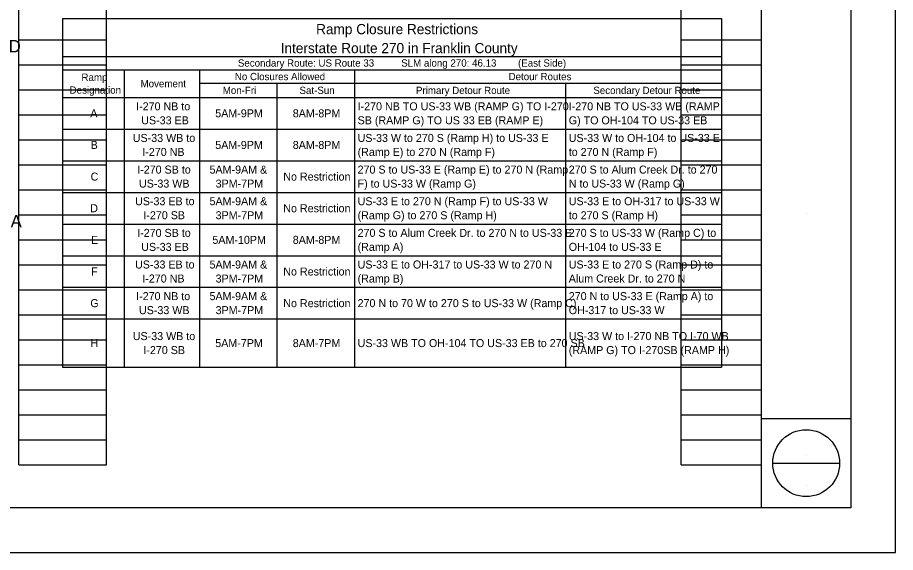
# Model space of a CAD drawing. Extents: x 0 to 34, y 0 to 22.
# Drawn here: x 24.17 to 34, y 0 to 5.99 of the extents above; entities that cross this region are included whole.
import ezdxf

# ---------------------------------------------------------------- set-up
doc = ezdxf.new("R2010")
doc.units = 0
for name, color, linetype in [('BD_P_Text', 7, 'Continuous'), ('Default', 7, 'Continuous'), ('SH_Border', 7, 'Continuous'), ('SH_Cut_Line', 7, 'Continuous'), ('SH_Data', 7, 'Continuous')]:
    doc.layers.add(name, color=color, linetype=linetype)

msp = doc.modelspace()

# ---------------------------------------------------------------- linework, layer by layer
at = {"layer": 'Default'}
for p, q in [((24.67, 5.9816), (32.05, 5.9816)), ((24.67, 5.9816), (24.67, 2.0745)), ((32.05, 5.9816), (32.05, 2.0745)), ((24.67, 5.5563), (32.05, 5.5563)), ((24.67, 5.4057), (32.05, 5.4057)), ((25.361, 5.4057), (25.361, 2.0745)), ((26.2027, 5.4057), (26.2027, 2.0745)), ((27.9392, 5.4057), (27.9392, 2.0745)), ((26.2027, 5.2551), (32.05, 5.2551)), ((27.0709, 5.2551), (27.0709, 2.0745)), ((30.3047, 5.2551), (30.3047, 2.0745)), ((24.67, 5.0956), (32.05, 5.0956)), ((24.67, 4.7412), (32.05, 4.7412)), ((24.67, 4.3868), (32.05, 4.3868)), ((24.67, 4.0325), (32.05, 4.0325)), ((24.67, 3.6781), (32.05, 3.6781)), ((24.67, 3.3237), (32.05, 3.3237)), ((24.67, 2.9693), (32.05, 2.9693)), ((24.67, 2.6149), (32.05, 2.6149)), ((24.67, 2.0745), (32.05, 2.0745))]:
    msp.add_line(p, q, dxfattribs=at)
at = {"layer": 'SH_Border'}
for p, q in [((32.5, 0.5), (32.5, 21.5)), ((32.5, 1.5), (33.5, 1.5))]:
    msp.add_line(p, q, dxfattribs=at)
msp.add_lwpolyline([(2, 21.5), (33.5, 21.5), (33.5, 0.5), (2, 0.5)], close=True, dxfattribs=at)
at = {"layer": 'SH_Cut_Line'}
msp.add_lwpolyline([(0, 0), (34, 0), (34, 22), (0, 22)], close=True, dxfattribs=at)
at = {"layer": 'SH_Data'}
for p, q in [((24.18, 0.98), (24.18, 21.14)), ((25.16, 0.98), (25.16, 21.14)), ((31.6, 0.98), (31.6, 21.14)), ((32.5, 0.98), (32.5, 21.14)), ((24.18, 5.74), (25.16, 5.74)), ((31.6, 5.74), (32.5, 5.74)), ((24.18, 5.46), (25.16, 5.46)), ((31.6, 5.46), (32.5, 5.46)), ((24.18, 5.18), (25.16, 5.18)), ((31.6, 5.18), (32.5, 5.18)), ((24.18, 4.9), (25.16, 4.9)), ((31.6, 4.9), (32.5, 4.9)), ((24.18, 4.62), (25.16, 4.62)), ((31.6, 4.62), (32.5, 4.62)), ((24.18, 4.34), (25.16, 4.34)), ((31.6, 4.34), (32.5, 4.34)), ((24.18, 4.06), (25.16, 4.06)), ((31.6, 4.06), (32.5, 4.06)), ((24.18, 3.78), (25.16, 3.78)), ((31.6, 3.78), (32.5, 3.78)), ((33, 3.7917), (33, 3.7917)), ((24.18, 3.5), (25.16, 3.5)), ((31.6, 3.5), (32.5, 3.5)), ((24.18, 3.22), (25.16, 3.22)), ((31.6, 3.22), (32.5, 3.22)), ((24.18, 2.94), (25.16, 2.94)), ((31.6, 2.94), (32.5, 2.94)), ((24.18, 2.66), (25.16, 2.66)), ((31.6, 2.66), (32.5, 2.66)), ((24.18, 2.38), (25.16, 2.38)), ((31.6, 2.38), (32.5, 2.38)), ((24.18, 2.1), (25.16, 2.1)), ((31.6, 2.1), (32.5, 2.1)), ((24.18, 1.82), (25.16, 1.82)), ((31.6, 1.82), (32.5, 1.82)), ((24.18, 1.54), (25.16, 1.54)), ((31.6, 1.54), (32.5, 1.54)), ((24.18, 1.26), (25.16, 1.26)), ((31.6, 1.26), (32.5, 1.26)), ((33, 1.085), (33, 1.085)), ((32.625, 1), (33.375, 1)), ((24.18, 0.98), (25.16, 0.98)), ((31.6, 0.98), (32.5, 0.98)), ((33, 0.745), (33, 0.745))]:
    msp.add_line(p, q, dxfattribs=at)
msp.add_circle((33, 1), 0.375, dxfattribs=at)

# ---------------------------------------------------------------- texts
at = {"layer": 'BD_P_Text'}
for s, p in [('DAMAGED ', (23.2546, 5.6)), ('A ', (24.0879, 3.64))]:
    msp.add_text(s, height=0.14, dxfattribs=at).set_placement(p)
at = {"layer": 'Default'}
for s, height, p in [('Ramp Closure Restrictions', 0.114111, (27.5097, 5.8044)), ('Interstate Route 270 in Franklin County', 0.114111, (27.1128, 5.5917)), ('Secondary Route: US Route 33          SLM along 270: 46.13        (East Side)', 0.081508, (26.6333, 5.4411)), ('Ramp', 0.08151, (24.8809, 5.2812)), ('No Closures Allowed', 0.081508, (26.5991, 5.2896)), ('Detour Routes', 0.081508, (29.6662, 5.2896)), ('Designation', 0.081508, (24.7485, 5.1386)), ('Movement', 0.08151, (25.5431, 5.2099)), ('Mon-Fri', 0.08151, (26.4638, 5.1346)), ('Sat-Sun', 0.08151, (27.3235, 5.1346)), ('Primary Detour Route', 0.081508, (28.6286, 5.1346)), ('Secondary Detour Route', 0.081508, (30.6156, 5.1346)), ('I-270 NB to', 0.089659, (25.4934, 4.952)), ('I-270 NB TO US-33 WB (RAMP G) TO I-270', 0.089659, (27.9746, 4.952)), ('I-270 NB TO US-33 WB (RAMP', 0.089659, (30.3401, 4.952)), ('A', 0.0897, (24.9798, 4.8736)), ('5AM-9PM', 0.08966, (26.3799, 4.8736)), ('8AM-8PM', 0.08966, (27.2482, 4.8736)), ('US-33 EB', 0.08966, (25.5508, 4.7951)), ('SB (RAMP G) TO US 33 EB (RAMP E)', 0.089659, (27.9746, 4.7951)), ('G) TO OH-104 TO US-33 EB', 0.089659, (30.3401, 4.7951)), ('US-33 WB to', 0.089659, (25.4561, 4.5977)), ('US-33 W to 270 S (Ramp H) to US-33 E', 0.089659, (27.9746, 4.5977)), ('US-33 W to OH-104 to US-33 E', 0.089659, (30.3401, 4.5977)), ('B', 0.0897, (24.9837, 4.5192)), ('I-270 NB', 0.08966, (25.5626, 4.4408)), ('5AM-9PM', 0.08966, (26.3799, 4.5192)), ('8AM-8PM', 0.08966, (27.2482, 4.5192)), ('(Ramp E) to 270 N (Ramp F)', 0.089659, (27.9746, 4.4408)), ('to 270 N (Ramp F)', 0.089659, (30.3401, 4.4408)), ('I-270 SB to', 0.089659, (25.5052, 4.2433)), ('5AM-9AM &', 0.08966, (26.3156, 4.2433)), ('270 S to US-33 E (Ramp E) to 270 N (Ramp', 0.089659, (27.9746, 4.2433)), ('270 S to Alum Creek Dr. to 270', 0.089659, (30.3401, 4.2433)), ('C', 0.0897, (24.9834, 4.1648)), ('No Restriction', 0.089659, (27.142, 4.1648)), ('US-33 WB', 0.08966, (25.5252, 4.0864)), ('3PM-7PM', 0.08966, (26.3839, 4.0864)), ('F) to US-33 W (Ramp G)', 0.089659, (27.9746, 4.0864)), ('N to US-33 W (Ramp G)', 0.089659, (30.3401, 4.0864)), ('US-33 EB to', 0.089659, (25.4816, 3.8889)), ('5AM-9AM &', 0.08966, (26.3156, 3.8889)), ('US-33 E to 270 N (Ramp F) to US-33 W', 0.089659, (27.9746, 3.8889)), ('US-33 E to OH-317 to US-33 W', 0.089659, (30.3401, 3.8889)), ('D', 0.0897, (24.9793, 3.8104)), ('No Restriction', 0.089659, (27.142, 3.8104)), ('I-270 SB', 0.08966, (25.5744, 3.732)), ('3PM-7PM', 0.08966, (26.3839, 3.732)), ('(Ramp G) to 270 S (Ramp H)', 0.089659, (27.9746, 3.732)), ('to 270 S (Ramp H)', 0.089659, (30.3401, 3.732)), ('E', 0.0897, (24.9878, 3.4561)), ('I-270 SB to', 0.089659, (25.5052, 3.5345)), ('5AM-10PM', 0.08966, (26.3477, 3.4561)), ('8AM-8PM', 0.08966, (27.2482, 3.4561)), ('270 S to Alum Creek Dr. to 270 N to US-33 E', 0.089659, (27.9746, 3.5345)), ('270 S to US-33 W (Ramp C) to', 0.089659, (30.3401, 3.5345)), ('US-33 EB', 0.08966, (25.5508, 3.3776)), ('(Ramp A)', 0.08966, (27.9746, 3.3776)), ('OH-104 to US-33 E', 0.089659, (30.3401, 3.3776)), ('US-33 EB to', 0.089659, (25.4816, 3.1801)), ('5AM-9AM &', 0.08966, (26.3156, 3.1801)), ('US-33 E to OH-317 to US-33 W to 270 N', 0.089659, (27.9746, 3.1801)), ('US-33 E to 270 S (Ramp D) to', 0.089659, (30.3401, 3.1801)), ('F', 0.0897, (24.9891, 3.1017)), ('No Restriction', 0.089659, (27.142, 3.1017)), ('I-270 NB', 0.08966, (25.5626, 3.0232)), ('3PM-7PM', 0.08966, (26.3839, 3.0232)), ('(Ramp B)', 0.08966, (27.9746, 3.0232)), ('Alum Creek Dr. to 270 N', 0.089659, (30.3401, 3.0232)), ('I-270 NB to', 0.089659, (25.4934, 2.8258)), ('5AM-9AM &', 0.08966, (26.3156, 2.8258)), ('270 N to US-33 E (Ramp A) to', 0.089659, (30.3401, 2.8258)), ('G', 0.0897, (24.98, 2.7473)), ('US-33 WB', 0.08966, (25.5252, 2.6688)), ('3PM-7PM', 0.08966, (26.3839, 2.6688)), ('No Restriction', 0.089659, (27.142, 2.7473)), ('270 N to 70 W to 270 S to US-33 W (Ramp C)', 0.089659, (27.9746, 2.7473)), ('OH-317 to US-33 W', 0.089659, (30.3401, 2.6688)), ('US-33 WB to', 0.089659, (25.4561, 2.3783)), ('US-33 W to I-270 NB TO I-70 WB', 0.089659, (30.3401, 2.3783)), ('H', 0.0897, (24.9812, 2.2999)), ('5AM-7PM', 0.08966, (26.3799, 2.2999)), ('8AM-7PM', 0.08966, (27.2482, 2.2999)), ('US-33 WB TO OH-104 TO US-33 EB to 270 SB', 0.089659, (27.9746, 2.2999)), ('I-270 SB', 0.08966, (25.5744, 2.2214)), ('(RAMP G) TO I-270SB (RAMP H)', 0.089659, (30.3401, 2.2214))]:
    msp.add_text(s, height=height, dxfattribs=at).set_placement(p)

doc.saveas('drawing.dxf')
